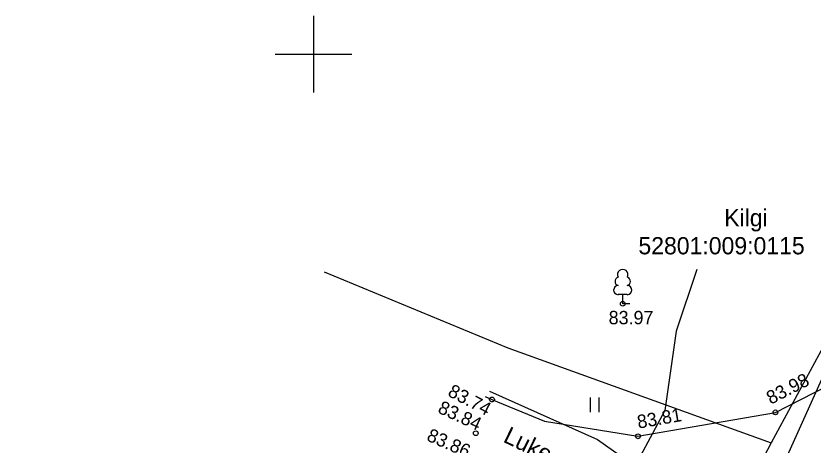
# Model space of a CAD drawing. Extents: x 648748 to 649126, y 6457789 to 6458252.
# Drawn here: x 648884.43 to 648926.14, y 6458229.55 to 6458252 of the extents above; entities that cross this region are included whole.
import ezdxf

# ---------------------------------------------------------------- set-up
doc = ezdxf.new("R2010")
doc.units = 0
for name, color, linetype in [('HALJASTUS', 7, 'Continuous'), ('KORGUS-EH2000', 7, 'Continuous'), ('PIIR', 7, 'Continuous'), ('PUU', 7, 'Continuous'), ('SITRASS', 7, 'Continuous'), ('TEE', 7, 'Continuous'), ('VORK', 7, 'Continuous'), ('VTRASS', 7, 'Continuous')]:
    doc.layers.add(name, color=color, linetype=linetype)

msp = doc.modelspace()

# ---------------------------------------------------------------- linework, layer by layer
at = {"layer": 'HALJASTUS'}
for p, q in [((648914.478, 6458232.034), (648914.478, 6458231.273)), ((648914.933, 6458232.034), (648914.933, 6458231.273))]:
    msp.add_line(p, q, dxfattribs=at)
at = {"layer": 'KORGUS-EH2000'}
for centre in [(648916.177, 6458236.944), (648909.335, 6458231.935), (648924.168, 6458231.261), (648908.488, 6458230.169), (648916.975, 6458230.01)]:
    msp.add_circle(centre, 0.125, dxfattribs=at)
at = {"layer": 'PIIR'}
for p, q in [((648932.763, 6458246.008), (648923.94, 6458229.66)), ((648900.554, 6458238.618), (648910.17, 6458234.64)), ((648910.17, 6458234.64), (648923.94, 6458229.66)), ((648923.94, 6458229.66), (648919.27, 6458220.73))]:
    msp.add_line(p, q, dxfattribs=at)
at = {"layer": 'PUU'}
for p, q in [((648916.417, 6458237.419), (648915.937, 6458237.419)), ((648916.177, 6458236.944), (648916.177, 6458237.419)), ((648916.557, 6458236.944), (648916.177, 6458236.944))]:
    msp.add_line(p, q, dxfattribs=at)
for centre, radius, start, end in [((648916.177, 6458238.464), 0.277, 332.58, 207.42), ((648916.007, 6458238.116), 0.233, 109.022, 253.142), ((648916.347, 6458238.116), 0.233, 286.851, 70.986), ((648915.94, 6458237.656), 0.238, 90.002, 269.395), ((648916.415, 6458237.656), 0.238, 270.605, 89.998)]:
    msp.add_arc(centre, radius, start, end, dxfattribs=at)
at = {"layer": 'SITRASS'}
for points in [[(648929.925, 6458240.085), (648929.233, 6458238.833), (648926.729, 6458233.327), (648923.21, 6458225.506), (648918.966, 6458215.361), (648917.027, 6458210.342), (648911.341, 6458199.533), (648902.157, 6458183.584), (648896.992, 6458174.764), (648890.118, 6458163.377), (648888.523, 6458160), (648880.878, 6458146.779), (648876.372, 6458138.998), (648873.186, 6458136.533), (648872.398, 6458135.159), (648870.194, 6458131.921), (648868.778, 6458129.583), (648863.975, 6458121.708)], [(648920.046, 6458238.741), (648918.974, 6458235.501), (648918.374, 6458231.362), (648916.343, 6458227.563), (648914.757, 6458225.445), (648913.89, 6458223.662), (648910.648, 6458217.515), (648906.266, 6458207.122), (648902.537, 6458197.956), (648897.439, 6458185.518), (648896.343, 6458186.017)]]:
    msp.add_lwpolyline(points, dxfattribs=at)
at = {"layer": 'TEE'}
msp.add_lwpolyline([(648908.971, 6458232.095), (648909.335, 6458231.935), (648912.092, 6458230.8), (648916.975, 6458230.01), (648924.168, 6458231.261), (648929.571, 6458234.023), (648933.29, 6458237.096), (648933.676, 6458237.527)], dxfattribs=at)
at = {"layer": 'VORK'}
for p, q in [((648900, 6458252), (648900, 6458248)), ((648898, 6458250), (648902, 6458250))]:
    msp.add_line(p, q, dxfattribs=at)
at = {"layer": 'VTRASS'}
msp.add_lwpolyline([(648909.205, 6458232.372), (648914.854, 6458229.849), (648928.414, 6458220.256), (648945.257, 6458202.659), (648946.152, 6458201.5), (648950.981, 6458195.246), (648957.402, 6458181.131), (648957.363, 6458178.163), (648955.762, 6458171.425), (648951.333, 6458156.349), (648957.558, 6458132.798)], dxfattribs=at)

# ---------------------------------------------------------------- texts
at = {"layer": 'KORGUS-EH2000'}
msp.add_text('83.97', height=0.7, dxfattribs=at).set_placement((648915.441, 6458235.87))
for s, rotation, p in [('83.98', 27.0815, (648923.922, 6458231.657)), ('83.74', 332.3217, (648906.973, 6458232.152)), ('83.84', 335.2019, (648906.453, 6458231.268)), ('83.81', 9.8633, (648916.998, 6458230.41)), ('83.86', 336.2167, (648905.868, 6458229.81))]:
    msp.add_text(s, height=0.7, rotation=rotation, dxfattribs=at).set_placement(p)
at = {"layer": 'PIIR'}
for s, rotation, p in [('Kilgi', 360, (648921.489, 6458240.994)), ('52801:009:0115', 360, (648916.998, 6458239.529)), ('Luke-Aarike tee L1', 334.0385, (648909.871, 6458229.742))]:
    msp.add_text(s, height=0.9, rotation=rotation, dxfattribs=at).set_placement(p)

doc.saveas('drawing.dxf')
